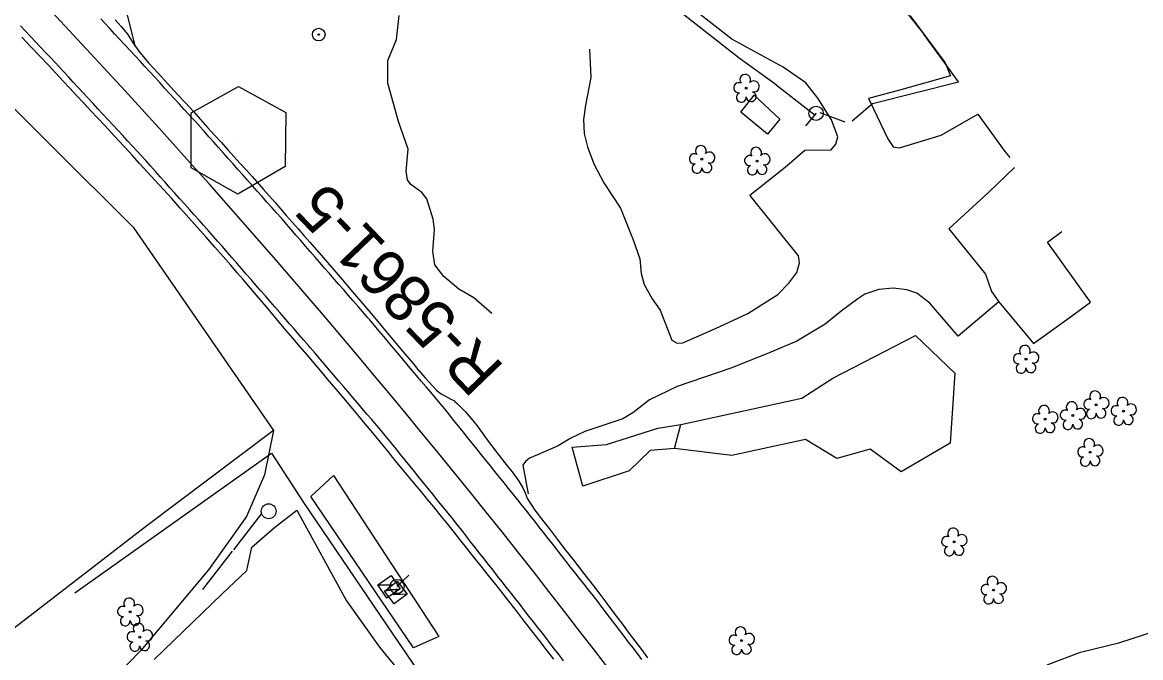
# Model space of a CAD drawing. Extents: x 474972 to 479313, y 498315 to 502691.
# Drawn here: x 477234.5 to 477618.9, y 499953.8 to 500171.9 of the extents above; entities that cross this region are included whole.
import ezdxf

# ---------------------------------------------------------------- set-up
doc = ezdxf.new("R2010")
doc.units = 0
for name, color, linetype in [('CTL Primary Horizontal and Vertical CELL', 7, 'Continuous'), ('CTL Primary Horizontal and Vertical Text', 7, 'Continuous'), ('Exist Horizontal Alignment', 7, 'Continuous'), ('Exist Other Culture Fence Line', 7, 'Continuous'), ('Exist Other Culture Gate', 7, 'Continuous'), ('Exist Other Culture Sign', 7, 'Continuous'), ('Exist Other Culture Well CELL', 7, 'Continuous'), ('Exist Roads EOP', 7, 'Continuous'), ('Exist Roads EOP Other', 7, 'Continuous'), ('Exist Roads EOT', 7, 'Continuous'), ('Exist Roads Soil', 7, 'Continuous'), ('Exist Utilities Other Located Object CELL', 7, 'Continuous'), ('Exist Utilities Power Pole CELL', 7, 'Continuous'), ('Exist Utilities Power Transformer CELL', 7, 'Continuous'), ('Exist Vegetation Hedge Row', 7, 'Continuous'), ('Exist Vegetation Tree CELL', 7, 'Continuous'), ('Exist Vegetation Woods Line', 7, 'Continuous')]:
    doc.layers.add(name, color=color, linetype=linetype)

msp = doc.modelspace()

# ---------------------------------------------------------------- linework, layer by layer
at = {"layer": 'CTL Primary Horizontal and Vertical CELL'}
msp.add_line((477308.68, 500131.56), (477308.68, 500131.56), dxfattribs=at)
msp.add_lwpolyline([(477292.52, 500140.92), (477308.77, 500149.98), (477325.02, 500141.05), (477324.77, 500122.42), (477308.52, 500112.98), (477292.52, 500122.05)], close=True, dxfattribs=at)
at = {"layer": 'Exist Horizontal Alignment'}
msp.add_arc((475159.06, 498211.82), 2864.54, 37.33366, 48.4381, dxfattribs=at)
at = {"layer": 'Exist Other Culture Fence Line'}
msp.add_line((477493.59, 500150.54), (477507, 500140.12), dxfattribs=at)
for points in [[(477493.59, 500150.54), (477480.89, 500159.66), (477457.6, 500177.83), (477508.16, 500213.44), (477544.32, 500167.89)], [(477526.74, 500144.07), (477556.22, 500151.53), (477544.32, 500167.89)], [(477252.46, 499976.08), (477320.07, 500023.97), (477331.36, 500006.71), (477363.76, 499959.01), (477380.88, 499934.01), (477403.42, 499901.35)]]:
    msp.add_lwpolyline(points, dxfattribs=at)
at = {"layer": 'Exist Other Culture Gate'}
for p, q in [((477519.66, 500138.18), (477526.74, 500144.07)), ((477508.58, 500140.95), (477517.23, 500137.76))]:
    msp.add_line(p, q, dxfattribs=at)
at = {"layer": 'Exist Other Culture Sign'}
for p, q in [((477307.17, 499990.79), (477316.83, 500003.28)), ((477296.54, 499977.19), (477306.66, 499990.32))]:
    msp.add_line(p, q, dxfattribs=at)
at = {"layer": 'Exist Other Culture Well CELL'}
msp.add_circle((477319.15, 500004.07), 2.56, dxfattribs=at)
at = {"layer": 'Exist Roads EOP'}
for points in [[(477266.33, 500172.8), (477268.45, 500170.49), (477270.66, 500167.91), (477272.82, 500164.45), (477274.9, 500161.61), (477277.87, 500158.08), (477281.23, 500154.37), (477283.29, 500152.13), (477285.51, 500149.71), (477287.92, 500147.09), (477290.5, 500144.29), (477293.13, 500141.42), (477295.68, 500138.62), (477298.16, 500135.89), (477300.57, 500133.23), (477302.9, 500130.65), (477305.15, 500128.17), (477307.31, 500125.78), (477309.39, 500123.5), (477311.41, 500121.26), (477313.43, 500119.03), (477317.41, 500114.55), (477321.36, 500110.06), (477323.34, 500107.8), (477325.31, 500105.54), (477327.29, 500103.27), (477329.27, 500101), (477331.26, 500098.72), (477333.25, 500096.44), (477337.13, 500091.98), (477340.8, 500087.75), (477344.37, 500083.62), (477347.96, 500079.45), (477351.49, 500075.32), (477354.89, 500071.3), (477358.27, 500067.28), (477361.73, 500063.16), (477365.25, 500058.96), (477368.79, 500054.75), (477370.43, 500052.8), (477372.9, 500049.9), (477376.83, 500045.68), (477377.65, 500045), (477378.48, 500044.4), (477381.73, 500042.51), (477382.74, 500042.07), (477382.97, 500041.93), (477383.15, 500041.8), (477383.97, 500041.09), (477386.67, 500038.33), (477388.78, 500035.95), (477390.78, 500033.42), (477394.23, 500028.63), (477397.53, 500024.2), (477401.14, 500019.69), (477402.79, 500017.59), (477405.15, 500014.38), (477406.51, 500012.15), (477407.34, 500010.42), (477407.72, 500009.16), (477407.91, 500008.69), (477410.68, 500004.47), (477413.29, 500000.97), (477415.5, 499998.1), (477418.31, 499994.48), (477421.2, 499990.76), (477423.68, 499987.58), (477427.36, 499982.85), (477430.78, 499978.4), (477432.93, 499975.58), (477435.38, 499972.35), (477437.93, 499968.98), (477440.39, 499965.73), (477442.76, 499962.59), (477445.04, 499959.56), (477447.24, 499956.62), (477449.38, 499953.78)], [(477417.16, 499953.31), (477414.67, 499956.52), (477412.14, 499959.79), (477409.62, 499963.03), (477407.12, 499966.24), (477404.65, 499969.41), (477402.18, 499972.57), (477399.7, 499975.73), (477397.2, 499978.88), (477394.68, 499982.04), (477392.18, 499985.18), (477389.71, 499988.28), (477387.27, 499991.35), (477384.86, 499994.39), (477382.51, 499997.35), (477380.23, 500000.19), (477378.03, 500002.92), (477375.89, 500005.53), (477373.79, 500008.1), (477371.65, 500010.69), (477369.49, 500013.3), (477367.31, 500015.94), (477365.05, 500018.66), (477362.67, 500021.54), (477360.17, 500024.58), (477357.55, 500027.78), (477354.9, 500031.01), (477352.32, 500034.12), (477349.8, 500037.13), (477347.36, 500040.03), (477344.93, 500042.91), (477342.46, 500045.83), (477339.95, 500048.79), (477337.4, 500051.81), (477334.85, 500054.82), (477332.34, 500057.77), (477329.87, 500060.66), (477327.45, 500063.49), (477325.08, 500066.27), (477322.77, 500068.99), (477320.53, 500071.65), (477318.35, 500074.26), (477316.24, 500076.79), (477314.2, 500079.2), (477310.36, 500083.7), (477308.36, 500085.99), (477306.08, 500088.61), (477303.5, 500091.54), (477300.64, 500094.79), (477297.64, 500098.18), (477294.65, 500101.55), (477291.68, 500104.88), (477288.72, 500108.18), (477285.8, 500111.42), (477282.94, 500114.58), (477280.15, 500117.65), (477277.42, 500120.64), (477274.78, 500123.52), (477272.23, 500126.3), (477269.78, 500128.96), (477267.44, 500131.51), (477265.13, 500134.01), (477262.79, 500136.53), (477260.43, 500139.07), (477258.03, 500141.63), (477255.63, 500144.2), (477253.23, 500146.76), (477250.84, 500149.31), (477248.44, 500151.86), (477245.96, 500154.51), (477243.29, 500157.35), (477240.43, 500160.37), (477237.39, 500163.59), (477234.27, 500166.89)]]:
    msp.add_lwpolyline(points, dxfattribs=at)
at = {"layer": 'Exist Roads EOP Other'}
msp.add_lwpolyline([(477575.48, 500122.14), (477566.73, 500113.67), (477552.98, 500101.1), (477565.59, 500085.44), (477567.62, 500079.52), (477570.12, 500075.99), (477581.99, 500061.64), (477595.51, 500071.45), (477601.61, 500075.84), (477586.81, 500096.52), (477591.74, 500100.13)], dxfattribs=at)
at = {"layer": 'Exist Roads EOT'}
for points in [[(477420.47, 499952.73), (477418.95, 499954.71), (477417.43, 499956.7), (477415.91, 499958.68), (477414.4, 499960.67), (477413.25, 499962.16), (477411.71, 499964.13), (477410.17, 499966.09), (477408.62, 499968.06), (477407.08, 499970.02), (477405.54, 499971.99), (477404, 499973.95), (477402.45, 499975.92), (477400.91, 499977.88), (477399.37, 499979.85), (477397.82, 499981.81), (477396.28, 499983.78), (477394.74, 499985.75), (477393.19, 499987.71), (477391.65, 499989.68), (477390.11, 499991.64), (477388.57, 499993.61), (477387.02, 499995.57), (477385.48, 499997.54), (477383.94, 499999.5), (477382.39, 500001.47), (477381.82, 500002.2), (477380.24, 500004.14), (477378.67, 500006.08), (477377.09, 500008.02), (477375.52, 500009.96), (477373.94, 500011.9), (477372.37, 500013.84), (477370.79, 500015.77), (477369.22, 500017.71), (477367.64, 500019.65), (477366.06, 500021.59), (477364.49, 500023.53), (477362.91, 500025.47), (477361.34, 500027.41), (477359.76, 500029.35), (477358.19, 500031.29), (477357.8, 500031.76), (477356.18, 500033.66), (477354.56, 500035.56), (477352.93, 500037.46), (477351.31, 500039.36), (477349.69, 500041.26), (477348.06, 500043.16), (477346.44, 500045.06), (477344.82, 500046.96), (477343.19, 500048.86), (477341.57, 500050.76), (477339.95, 500052.66), (477338.32, 500054.56), (477336.7, 500056.46), (477335.07, 500058.36), (477333.45, 500060.26), (477332.79, 500061.03), (477331.15, 500062.92), (477329.51, 500064.8), (477327.86, 500066.69), (477326.22, 500068.57), (477324.58, 500070.46), (477322.94, 500072.34), (477321.3, 500074.23), (477319.66, 500076.11), (477318.02, 500077.99), (477316.37, 500079.88), (477314.73, 500081.76), (477313.09, 500083.65), (477311.45, 500085.53), (477309.81, 500087.42), (477308.17, 500089.3), (477306.53, 500091.18), (477304.89, 500093.07), (477303.24, 500094.95), (477301.6, 500096.84), (477300.21, 500098.44), (477298.54, 500100.3), (477296.87, 500102.16), (477295.2, 500104.02), (477293.54, 500105.88), (477291.87, 500107.74), (477290.2, 500109.6), (477288.53, 500111.46), (477286.86, 500113.32), (477285.2, 500115.18), (477283.53, 500117.04), (477281.86, 500118.9), (477280.19, 500120.76), (477278.52, 500122.63), (477276.86, 500124.49), (477275.19, 500126.35), (477274.05, 500127.61), (477272.35, 500129.45), (477270.66, 500131.28), (477268.96, 500133.12), (477267.26, 500134.95), (477265.56, 500136.78), (477263.87, 500138.62), (477262.17, 500140.45), (477260.47, 500142.29), (477258.77, 500144.12), (477257.08, 500145.95), (477255.38, 500147.79), (477253.68, 500149.62), (477251.99, 500151.46), (477250.29, 500153.29), (477248.59, 500155.13), (477246.89, 500156.96), (477245.9, 500158.04), (477244.18, 500159.85), (477242.46, 500161.66), (477240.74, 500163.48), (477239.02, 500165.29), (477237.3, 500167.1), (477235.58, 500168.92), (477233.86, 500170.73)], [(477447.44, 499953.2), (477445.92, 499955.18), (477444.4, 499957.17), (477442.88, 499959.15), (477441.36, 499961.13), (477439.84, 499963.11), (477438.32, 499965.1), (477436.8, 499967.08), (477435.28, 499969.06), (477433.76, 499971.05), (477432.24, 499973.03), (477430.67, 499975.08), (477429.12, 499977.04), (477427.58, 499979.01), (477426.03, 499980.97), (477424.48, 499982.93), (477422.94, 499984.9), (477421.39, 499986.86), (477419.85, 499988.82), (477418.3, 499990.79), (477416.76, 499992.75), (477415.21, 499994.72), (477413.67, 499996.68), (477412.12, 499998.64), (477410.58, 500000.61), (477409.03, 500002.57), (477407.49, 500004.53), (477406.3, 500006.05), (477404.73, 500008), (477403.17, 500009.94), (477401.6, 500011.89), (477400.04, 500013.84), (477398.47, 500015.79), (477396.91, 500017.74), (477395.34, 500019.68), (477393.78, 500021.63), (477392.21, 500023.58), (477390.65, 500025.53), (477389.08, 500027.48), (477387.52, 500029.43), (477385.95, 500031.37), (477384.39, 500033.32), (477382.82, 500035.27), (477381.26, 500037.22), (477379.67, 500039.2), (477378.05, 500041.11), (477376.44, 500043.02), (477374.83, 500044.93), (477373.22, 500046.84), (477371.61, 500048.75), (477370, 500050.66), (477368.39, 500052.57), (477366.78, 500054.48), (477365.17, 500056.39), (477363.55, 500058.3), (477361.94, 500060.21), (477360.33, 500062.12), (477358.72, 500064.03), (477357.11, 500065.94), (477355.5, 500067.84), (477353.89, 500069.75), (477353.15, 500070.63), (477351.51, 500072.52), (477349.87, 500074.4), (477348.22, 500076.28), (477346.58, 500078.17), (477344.94, 500080.05), (477343.3, 500081.94), (477341.66, 500083.82), (477340.02, 500085.71), (477338.38, 500087.59), (477336.74, 500089.47), (477335.1, 500091.36), (477333.45, 500093.24), (477331.81, 500095.13), (477330.17, 500097.01), (477328.53, 500098.9), (477326.89, 500100.78), (477325.25, 500102.67), (477323.61, 500104.55), (477323.51, 500104.66), (477321.85, 500106.53), (477320.19, 500108.4), (477318.54, 500110.26), (477316.88, 500112.13), (477315.22, 500114), (477313.56, 500115.87), (477311.9, 500117.74), (477310.24, 500119.61), (477308.58, 500121.47), (477306.92, 500123.34), (477305.26, 500125.21), (477303.6, 500127.08), (477301.94, 500128.95), (477300.28, 500130.82), (477298.62, 500132.68), (477296.96, 500134.55), (477295.3, 500136.42), (477295.21, 500136.53), (477293.52, 500138.37), (477291.83, 500140.21), (477290.14, 500142.05), (477288.44, 500143.89), (477286.75, 500145.73), (477285.06, 500147.57), (477283.37, 500149.41), (477281.68, 500151.26), (477279.99, 500153.1), (477278.3, 500154.94), (477276.61, 500156.78), (477274.92, 500158.62), (477273.23, 500160.46), (477271.54, 500162.3), (477269.85, 500164.14), (477269.61, 500164.4), (477267.91, 500166.23), (477266.2, 500168.06), (477264.5, 500169.89), (477262.8, 500171.72), (477261.4, 500173.22)]]:
    msp.add_lwpolyline(points, dxfattribs=at)
at = {"layer": 'Exist Roads Soil'}
for points in [[(477428.05, 500143.48), (477427.41, 500138.57), (477427.56, 500133.77), (477428.75, 500129.17), (477430.92, 500123.33), (477434.36, 500116.82), (477440.1, 500108.16), (477441.65, 500104.19), (477444.39, 500097.31), (477446.69, 500090.72), (477447.23, 500085.77), (477448.26, 500081.94), (477450.95, 500077), (477453.7, 500073.16), (477457.68, 500062.84), (477459.5, 500061.74), (477461.55, 500061.96), (477472.75, 500066.84), (477483.82, 500072.02), (477494.2, 500078.48), (477497.97, 500082.36), (477500.67, 500086.02), (477501.56, 500089.41), (477501.29, 500091.77), (477484.52, 500112.62), (477496.64, 500122.23), (477503.39, 500128.06), (477512.48, 500128.23), (477514.14, 500130.11), (477514.73, 500132.66), (477512.58, 500138.54), (477507.95, 500145.87), (477503.78, 500151.19), (477495.97, 500156.61), (477478.37, 500166.21), (477461.76, 500179.1)], [(477270.34, 500174.9), (477273.29, 500163.54)], [(477367.04, 500128.45), (477363.78, 500137.88), (477360.06, 500151.07), (477360.09, 500158.91), (477363.13, 500166.11), (477364.03, 500174.34)], [(477539.61, 500174.25), (477551.7, 500158.05), (477553.48, 500153.56), (477536.46, 500148.78), (477525.33, 500145.77), (477527.05, 500142.24), (477531.94, 500131.93), (477533.84, 500129.23), (477535.94, 500128.84), (477550.25, 500133.2), (477562.9, 500140.44), (477572.2, 500127.61), (477573.92, 500125.55)], [(477429.44, 500162.77), (477429.92, 500152.99), (477428.05, 500143.48)], [(477395.88, 500072.01), (477389.69, 500077.32), (477384.54, 500080.34), (477379.37, 500084.64), (477376.29, 500088.69), (477375.56, 500093.39), (477376.11, 500100.81), (477375.69, 500104.36), (477373.48, 500111.33), (477371.82, 500113.54), (477368.01, 500116.3), (477366.91, 500117.83), (477366.45, 500120.85), (477367.04, 500128.45)], [(477570.12, 500075.99), (477556.17, 500064.21), (477546.4, 500075.5), (477541.97, 500078.95), (477538.46, 500080.16), (477533.79, 500080.65), (477528.9, 500080.25), (477524.07, 500078.61), (477521.63, 500077.07), (477515.96, 500072.77), (477510.41, 500068.28), (477500.7, 500062.46), (477490.39, 500058.09), (477478.01, 500053.25), (477459.61, 500046.87), (477450.08, 500042.28), (477444.28, 500037.87), (477440.9, 500035.77), (477427.8, 500031.5), (477422.95, 500029.16), (477418.64, 500026.56), (477411.51, 500023.45), (477408.74, 500022.35), (477407.42, 500021.21), (477406.52, 500019.94), (477408.34, 500010.09)], [(477279.78, 499953.17), (477303.19, 499975.71), (477311.65, 499983.7), (477313.31, 499991.69), (477321.1, 499998.45), (477328.84, 500004.48), (477345.9, 499973.31), (477357.18, 499957.4), (477380.64, 499928.89)], [(477504.78, 499882.84), (477509.45, 499881.22), (477512.11, 499880.8), (477514.86, 499880.99), (477518.08, 499881.87), (477520.43, 499883.31), (477529.01, 499891.53), (477539.8, 499904.23), (477550.99, 499919.4), (477561.69, 499933.75), (477566.25, 499938.7), (477572.16, 499943.07), (477577.93, 499946.92), (477587.31, 499951.56), (477598.24, 499955.69), (477611.38, 499958.83), (477624.47, 499963.13)]]:
    msp.add_lwpolyline(points, dxfattribs=at)
at = {"layer": 'Exist Utilities Other Located Object CELL'}
for radius in [2.18, 0.24]:
    msp.add_circle((477336.34, 500167.78), radius, dxfattribs=at)
at = {"layer": 'Exist Utilities Power Pole CELL'}
for p, q in [((477507.31, 500140.74), (477503.65, 500136.48)), ((477507.31, 500140.74), (477507.31, 500140.74)), ((477363.24, 499978.22), (477367.28, 499982.13)), ((477363.24, 499978.22), (477363.24, 499978.22))]:
    msp.add_line(p, q, dxfattribs=at)
for centre in [(477507.31, 500140.74), (477363.24, 499978.22)]:
    msp.add_circle(centre, 2.45, dxfattribs=at)
at = {"layer": 'Exist Utilities Power Transformer CELL'}
for p, q in [((477360.68, 499978.17), (477360.68, 499978.17)), ((477362.65, 499976.08), (477362.65, 499976.08))]:
    msp.add_line(p, q, dxfattribs=at)
for points in [[(477361.22, 499981.99), (477364.36, 499977.41), (477359.78, 499974.27), (477356.64, 499978.85)], [(477362.29, 499972.23), (477358.93, 499976.66), (477363.36, 499980.01), (477366.71, 499975.59)]]:
    msp.add_lwpolyline(points, close=True, dxfattribs=at)
for points in [[(477356.64, 499978.85), (477361.39, 499978.9), (477359.92, 499977.13), (477364.36, 499977.41)], [(477356.68, 499978.79), (477361.22, 499978.78), (477359.75, 499977.06), (477364.24, 499977.32)], [(477366.71, 499975.59), (477361.97, 499975.31), (477363.35, 499977.15), (477358.93, 499976.66)], [(477366.67, 499975.64), (477362.14, 499975.44), (477363.52, 499977.22), (477359.06, 499976.75)]]:
    msp.add_lwpolyline(points, dxfattribs=at)
at = {"layer": 'Exist Vegetation Hedge Row'}
for points in [[(477486, 500146.91), (477494.86, 500138.7), (477490.6, 500133.58), (477481.41, 500141.13), (477486, 500146.91)], [(477458.67, 500025.67), (477450.3, 500024.89), (477443.01, 500017.96), (477427.1, 500012.63), (477423.46, 500026.13), (477435.3, 500027.02), (477452.89, 500032.58), (477460.83, 500033.83)], [(477320.82, 500031.77), (477317.76, 500016.55), (477311.47, 500002.27), (477298.41, 499983.94), (477275.15, 499956.26), (477245.99, 499926.25)], [(477341.39, 500016.39), (477377.65, 499961.09), (477368.88, 499957.13), (477333.65, 500009.12), (477341.39, 500016.39)]]:
    msp.add_lwpolyline(points, dxfattribs=at)
at = {"layer": 'Exist Vegetation Tree CELL'}
for p, q in [((477483.32, 500149.34), (477483.32, 500149.34)), ((477468.07, 500124.94), (477468.07, 500124.94)), ((477487.07, 500124.34), (477487.07, 500124.34)), ((477579.46, 500056.27), (477579.46, 500056.27)), ((477603.6, 500040.64), (477603.6, 500040.64)), ((477586.03, 500035.68), (477586.03, 500035.68)), ((477595.57, 500036.92), (477595.57, 500036.92)), ((477612.99, 500038.42), (477612.99, 500038.42)), ((477601.54, 500024.31), (477601.54, 500024.31)), ((477554.79, 499993.55), (477554.79, 499993.55)), ((477568.32, 499977.01), (477568.32, 499977.01)), ((477271.54, 499969.52), (477271.54, 499969.52)), ((477274.81, 499960.83), (477274.81, 499960.83)), ((477481.71, 499959.64), (477481.71, 499959.64))]:
    msp.add_line(p, q, dxfattribs=at)
for centre in [(477483.32, 500149.34), (477468.07, 500124.94), (477487.07, 500124.34), (477579.46, 500056.27), (477603.6, 500040.64), (477586.03, 500035.68), (477595.57, 500036.92), (477612.99, 500038.42), (477601.54, 500024.31), (477554.79, 499993.55), (477568.32, 499977.01), (477271.54, 499969.52), (477274.81, 499960.83), (477481.71, 499959.64)]:
    msp.add_circle(centre, 0.326, dxfattribs=at)
for centre, radius, start, end in [((477480.72, 500149.5), 1.73, 62.6636, 279.3457), ((477482.94, 500152.22), 1.86, 330.1651, 219.7134), ((477485.87, 500149.93), 1.9, 257.1011, 134.1999), ((477481.62, 500146.22), 1.69, 111.5671, 6.231), ((477485, 500146.44), 1.7, 181.2822, 74.56), ((477467.69, 500127.81), 1.86, 330.1651, 219.7134), ((477486.68, 500127.21), 1.86, 330.1651, 219.7134), ((477465.47, 500125.09), 1.73, 62.6636, 279.3457), ((477470.62, 500125.53), 1.9, 257.1011, 134.1999), ((477484.46, 500124.49), 1.73, 62.6636, 279.3457), ((477489.62, 500124.92), 1.9, 257.1011, 134.1999), ((477466.37, 500121.82), 1.69, 111.5671, 6.231), ((477469.75, 500122.04), 1.7, 181.2822, 74.56), ((477485.36, 500121.22), 1.69, 111.5671, 6.231), ((477488.74, 500121.44), 1.7, 181.2822, 74.56), ((477579.08, 500059.14), 1.86, 330.1651, 219.7134), ((477582.01, 500056.86), 1.9, 257.1011, 134.1999), ((477576.86, 500056.42), 1.73, 62.6636, 279.3457), ((477581.14, 500053.37), 1.7, 181.2822, 74.56), ((477577.76, 500053.15), 1.69, 111.5671, 6.231), ((477603.22, 500043.52), 1.86, 330.1651, 219.7134), ((477585.65, 500038.55), 1.86, 330.1651, 219.7134), ((477595.18, 500039.8), 1.86, 330.1651, 219.7134), ((477601, 500040.8), 1.73, 62.6636, 279.3457), ((477606.15, 500041.23), 1.9, 257.1011, 134.1999), ((477610.39, 500038.57), 1.73, 62.6636, 279.3457), ((477612.61, 500041.29), 1.86, 330.1651, 219.7134), ((477615.54, 500039.01), 1.9, 257.1011, 134.1999), ((477583.43, 500035.83), 1.73, 62.6636, 279.3457), ((477588.58, 500036.26), 1.9, 257.1011, 134.1999), ((477592.96, 500037.08), 1.73, 62.6636, 279.3457), ((477598.12, 500037.51), 1.9, 257.1011, 134.1999), ((477601.9, 500037.52), 1.69, 111.5671, 6.231), ((477605.27, 500037.74), 1.7, 181.2822, 74.56), ((477611.29, 500035.3), 1.69, 111.5671, 6.231), ((477614.67, 500035.52), 1.7, 181.2822, 74.56), ((477584.33, 500032.55), 1.69, 111.5671, 6.231), ((477587.71, 500032.78), 1.7, 181.2822, 74.56), ((477593.87, 500033.8), 1.69, 111.5671, 6.231), ((477597.24, 500034.02), 1.7, 181.2822, 74.56), ((477601.16, 500027.18), 1.86, 330.1651, 219.7134), ((477598.94, 500024.46), 1.73, 62.6636, 279.3457), ((477604.09, 500024.9), 1.9, 257.1011, 134.1999), ((477599.84, 500021.19), 1.69, 111.5671, 6.231), ((477603.21, 500021.41), 1.7, 181.2822, 74.56), ((477554.41, 499996.42), 1.86, 330.1651, 219.7134), ((477552.18, 499993.7), 1.73, 62.6636, 279.3457), ((477557.34, 499994.14), 1.9, 257.1011, 134.1999), ((477553.09, 499990.43), 1.69, 111.5671, 6.231), ((477556.46, 499990.65), 1.7, 181.2822, 74.56), ((477565.72, 499977.16), 1.73, 62.6636, 279.3457), ((477567.94, 499979.88), 1.86, 330.1651, 219.7134), ((477570.87, 499977.6), 1.9, 257.1011, 134.1999), ((477271.16, 499972.39), 1.86, 330.1651, 219.7134), ((477566.62, 499973.89), 1.69, 111.5671, 6.231), ((477570, 499974.11), 1.7, 181.2822, 74.56), ((477268.94, 499969.67), 1.73, 62.6636, 279.3457), ((477274.09, 499970.1), 1.9, 257.1011, 134.1999), ((477269.84, 499966.39), 1.69, 111.5671, 6.231), ((477273.22, 499966.62), 1.7, 181.2822, 74.56), ((477272.2, 499960.98), 1.73, 62.6636, 279.3457), ((477274.42, 499963.7), 1.86, 330.1651, 219.7134), ((477277.36, 499961.42), 1.9, 257.1011, 134.1999), ((477481.33, 499962.51), 1.86, 330.1651, 219.7134), ((477273.1, 499957.71), 1.69, 111.5671, 6.231), ((477276.48, 499957.93), 1.7, 181.2822, 74.56), ((477479.11, 499959.8), 1.73, 62.6636, 279.3457), ((477484.26, 499960.23), 1.9, 257.1011, 134.1999), ((477480.01, 499956.52), 1.69, 111.5671, 6.231), ((477483.38, 499956.74), 1.7, 181.2822, 74.56)]:
    msp.add_arc(centre, radius, start, end, dxfattribs=at)
at = {"layer": 'Exist Vegetation Woods Line'}
for points in [[(477215.96, 500157.8), (477272.51, 500101.65)], [(477272.51, 500101.65), (477320.82, 500031.77), (477276.76, 499998.69), (477220.98, 499955.77)], [(477513.03, 500049.73), (477541.53, 500064.39), (477555.04, 500051.47), (477553.37, 500027.42), (477536.53, 500017.55), (477525.95, 500025.37), (477514.45, 500022.19), (477503.68, 500028.67), (477478.3, 500023.21), (477458.67, 500025.67)], [(477460.83, 500033.83), (477502.38, 500042.87), (477513.03, 500049.73)], [(477458.67, 500025.67), (477460.83, 500033.83)]]:
    msp.add_lwpolyline(points, dxfattribs=at)

# ---------------------------------------------------------------- texts
at = {"layer": 'CTL Primary Horizontal and Vertical Text'}
msp.add_text('R-5861-5', height=16, rotation=133.908, dxfattribs=at).set_placement((477400.59, 500053.58))

doc.saveas('drawing.dxf')
